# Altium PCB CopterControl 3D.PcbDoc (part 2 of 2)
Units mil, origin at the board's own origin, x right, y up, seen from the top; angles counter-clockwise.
Board outline 1417.32 x 1417.32 mil, 2 copper layers (Top Layer, Bottom Layer), stack 61.2 mil thick; 64 components, 58 nets, 262 pads, 81 vias.
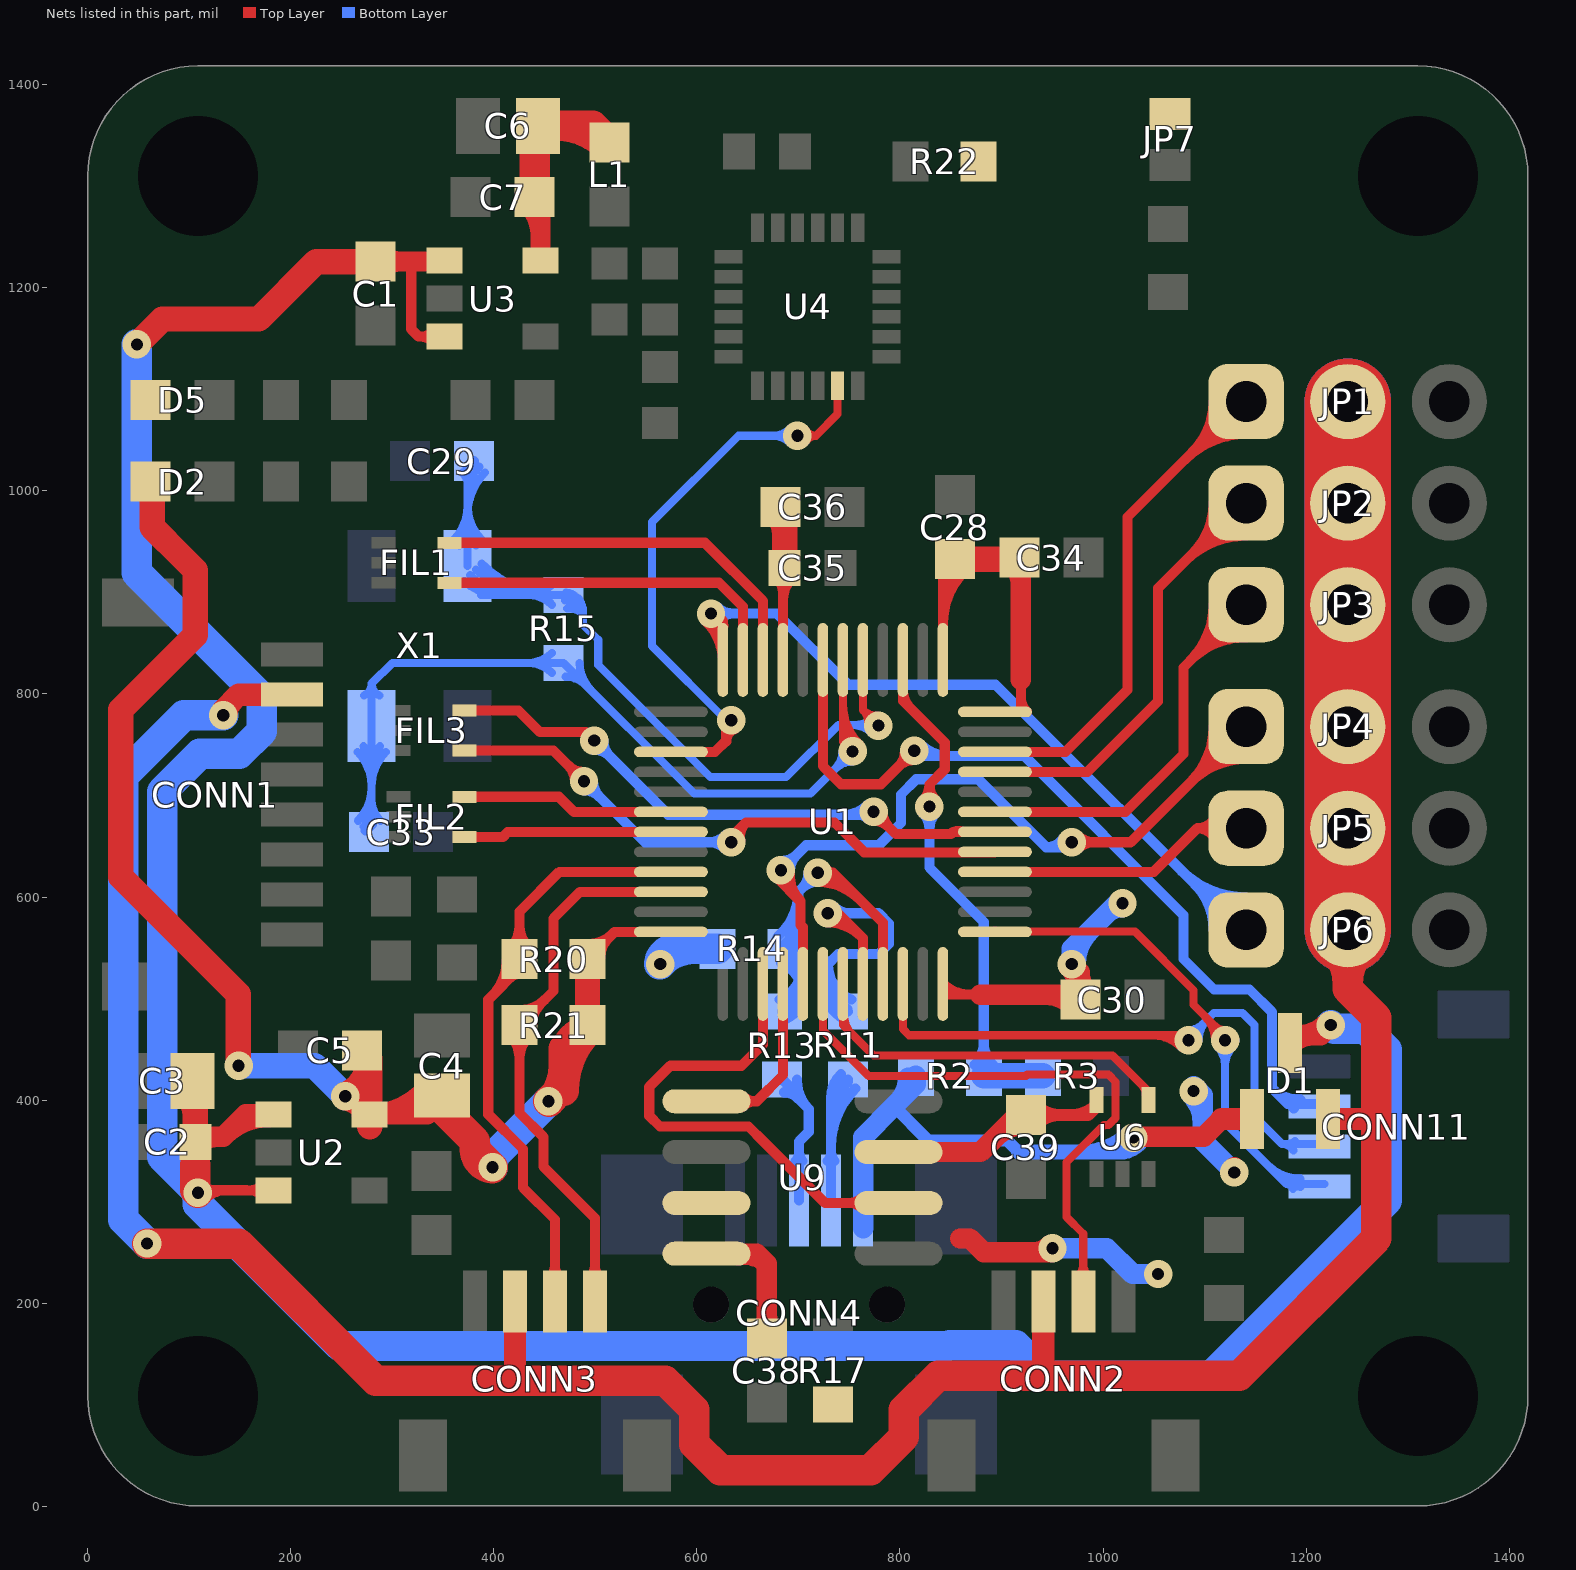
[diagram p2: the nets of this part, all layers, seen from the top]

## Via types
v1: diameter 28, hole 12, Top Layer to Bottom Layer, tented both sides, 81 vias

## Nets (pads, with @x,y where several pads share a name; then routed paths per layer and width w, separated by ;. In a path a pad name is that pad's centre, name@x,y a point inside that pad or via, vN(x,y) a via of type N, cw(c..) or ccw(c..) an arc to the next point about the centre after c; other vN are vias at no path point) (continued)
NetU1_27: U1.27 U9.2 | length 523.8
  Top Layer w10: U1.27@665.1,514.55 665.1,455.1 644,434 574,434 553.2,413.2 553.2,384.8 563.81,374.19 650.91,374.19 665.82,359.28 726.09,299 U9.2@798.49,299 ; U9.2@762.18,294.18 ccw(c750.55,282.56) 750.55,299 ccw(c750.55,315.44) U9.2@762.18,303.82
NetU1_28: U1.28 U9.5 | length 201.6
  Top Layer w10: U9.5@609.51,399 659,399 684.79,424.79 U1.28@684.79,514.55 ; U9.5@645.82,394.18 cw(c657.45,382.56) 657.45,399 cw(c657.45,415.44) U9.5@645.82,403.82
NRST: CONN11.2 U1.7 | length 942.4
  Top Layer w10: U1.7@724.16,833.45 724.16,728.84 742,711 781,711 809,739 814,739 v1(814,744) ; v1@805,744 cw(c783.27,744) 798.64,728.64 cw(c814,713.27) v1@814,735
  Bottom Layer w10: v1(814,744) 814,739 922.18,739 1079,582.18 1079,539 1109,509 1144,509 1166,487 1166,412 ; v1@820.36,750.36 ccw(c847.8,777.8) 847.8,739 ; CONN11.2@1187.64,391.83 ccw(c1181.58,390.12) 1181.58,396.42 ; CONN11.2@1194.13,400.5 cw(c1193.77,439.77) 1166,412 ; CONN11.2@1217.9,396.42 1181.58,396.42 ; 1166,412 1181.58,396.42
OSC_IN: C29.2 R15.2 U1.5 X1.3 | length 1407.7
  Top Layer w8: U1.5@763.53,833.45 763.53,784.07 ; v1@768.83,769.62 ccw(c750.57,771.12) 763.53,784.07 ; v1@777.98,778.77 cw(c776.48,797.02) 763.53,784.07 ; v1(778.8,768.8) 763.53,784.07
  Bottom Layer w8: X1.3@360.64,951.69 ccw(c327.14,985.19) 374.51,985.19 ccw(c421.88,985.19) X1.3@388.38,951.69 ; X1.3@366.29,946.04 ccw(c346.45,965.88) 374.51,965.88 ccw(c402.57,965.88) X1.3@382.73,946.04 ; C29.2@369.4,1017.91 cw(c357.08,1005.58) 374.51,1005.58 ; X1.3@371.41,911.1 ccw(c404.34,944.02) 404.34,897.46 ; X1.3@374.51,926.01 C29.2@374.51,1023.01 ; 374.51,976.68 cw(c432.81,976.68) C29.2@391.59,1017.91 ; 374.51,996 cw(c413.5,996) C29.2@385.93,1023.56 ; X1.3@377.07,916.76 ccw(c423.65,963.34) 423.65,897.47 ; X1.3@382.73,922.41 ccw(c442.96,982.65) 442.96,897.46 ; X1.3@387.47,897.47 R15.2@469,897.47 488,878.46 ; X1.3@388.38,928.07 ccw(c462.28,1001.96) R15.2@462.28,897.46 ; 432.29,902.86 ccw(c438.66,938.28) R15.2@459.2,908.73 ; 436.29,902.14 cw(c430.94,872.37) R15.2@455.77,889.64 ; R15.2@457.33,887.77 ccw(c433.92,864.35) 433.92,897.46 ccw(c433.92,930.58) R15.2@457.33,907.16 ; R15.2@470.42,891.77 cw(c468.57,872.43) 488,872.43 ; R15.2@471.19,899.74 cw(c469.41,881.24) R15.2@488,881.24 ; R15.2@472.55,883.84 cw(c474.72,865.18) 488,878.47 ; R15.2@484.13,893.61 ccw(c498.83,889.3) 488,878.46 ; 753.34,769.34 cw(c753.34,743.34) v1@771.73,761.73 ; 755.97,769.34 ccw(c755.97,791.63) v1@771.73,775.87 ; v1@769.32,765.6 ccw(c764.11,763.84) 764.11,769.34 ; v1@769.7,772.94 cw(c764.11,775.48) 764.11,769.34 ; v1(778.8,768.8) 778.14,768.14 765.31,768.14 764.11,769.34 ; 488,878.46 488,868.23 503,853.23 503,828.23 613.23,718 688,718 739.34,769.34 764.11,769.34
  Bottom Layer w10: C29.2@374.51,1023.01 C29.2@380.5,1029
OSC_OUT: C33.2 R15.1 U1.6 X1.1 | length 1238.7
  Top Layer w8: 743.84,771.11 ccw(c781.11,771.11) v1@754.76,744.76 ; 743.84,790.42 ccw(c800.42,790.42) v1@760.41,750.41 ; U1.6@743.84,833.45 743.84,752.84 v1(753.34,743.34)
  Bottom Layer w8: X1.1@266.15,742.84 cw(c232.65,709.34) 280.02,709.34 cw(c327.39,709.34) X1.1@293.9,742.84 ; C33.2@266.41,675.09 ccw(c233.55,707.95) 280.02,707.95 ; X1.1@271.8,748.5 cw(c251.96,728.66) 280.02,728.66 cw(c308.08,728.66) X1.1@288.24,748.5 ; C33.2@272.07,669.43 ccw(c252.87,688.63) 280.02,688.63 ; X1.1@272.33,798.39 ccw(c267.38,810.02) 280.02,810.02 ; C33.2@280.02,671.52 X1.1@280.02,768.53 280.02,810.02 ; 280.02,695.78 ccw(c309.29,695.78) C33.2@288.59,675.09 ; X1.1@287.71,798.39 cw(c292.66,810.02) 280.02,810.02 ; R15.1@457.33,820.84 ccw(c433.92,797.42) 433.92,830.53 ccw(c433.92,863.65) R15.1@457.33,840.23 ; R15.1@470.97,816.82 cw(c470.97,788.46) 491.02,808.51 ; R15.1@484.68,830.53 ccw(c522.55,830.53) 495.78,803.76 ; v1@743.34,743.34 cw(c719.2,743.34) 736.27,726.27 cw(c753.34,709.2) v1@753.34,733.34 ; v1@754,744 v1(753.34,743.34) 712,702 597.53,702 R15.1@469,830.53 300.53,830.53 280.02,810.02
  Bottom Layer w10: C33.2@274,665.5 C33.2@280.02,671.52
S1_IN: FIL3.5 U1.42 | length 691.1
  Top Layer w10: FIL3.5@371.48,783.69 424.31,783.69 445.68,762.32 490.68,762.32 v1(499,754) ; v1@774,675 cw(c774,653.27) 789.36,668.64 cw(c804.73,684) v1@783,684 ; v1(774,684) 796,662 850.18,662 ; U1.42@862.15,663.96 ccw(c857.54,654.65) 850.18,662 ; U1.42@893.45,664.16 852.34,664.16 850.18,662
  Bottom Layer w10: v1@499,745 cw(c499,723.27) 514.36,738.64 cw(c529.73,754) v1@508,754 ; v1(499,754) 572,681 771,681 v1(774,684) ; 745.03,681 ccw(c745.03,712.97) v1@767.64,690.36 ; 759.51,681 cw(c759.51,669.51) v1@767.64,677.64
S1_OUT: JP1.1 U1.46 | length 694.5
  Top Layer w10: U1.46@893.45,742.9 962.9,742.9 1024,804 1024,974 1137.73,1087.73 JP1.1@1140.73,1087.73 ; 1080.99,1030.99 cw(c1140.73,971.24) JP1.1@1140.73,1055.73 ; 1088.23,1038.23 ccw(c1038.72,1087.73) JP1.1@1108.73,1087.73 ; 1098.06,1048.06 cw(c1140.73,1005.38) JP1.1@1140.73,1065.73 ; 1105.3,1055.3 ccw(c1072.86,1087.73) JP1.1@1118.73,1087.73
S2_IN: FIL3.4 U1.41 | length 704.3
  Top Layer w10: FIL3.4@371.48,744.32 458.68,744.32 v1(489,714) ; v1@480,714 ccw(c458.27,714) 473.64,729.36 ccw(c489,744.73) v1@489,723 ; v1(634,654) 634,659 648.32,673.32 ; v1@642.85,655.65 cw(c662.33,659.3) 648.32,673.32 ; U1.41@893.45,644.47 892.98,644 764.91,644 735.6,673.32 648.32,673.32
  Bottom Layer w10: v1@489,705 cw(c489,683.27) 504.36,698.64 cw(c519.73,714) v1@498,714 ; v1(489,714) 549,654 v1(634,654) ; v1@627.64,647.64 ccw(c612.27,632.27) 612.27,654 ccw(c612.27,675.73) v1@627.64,660.36
S2_OUT: JP2.1 U1.45 | length 626.9
  Top Layer w10: U1.45@893.45,723.21 984.57,723.21 1054,792.64 1054,904 1137.73,987.73 JP2.1@1140.73,987.73 ; 1080.99,930.99 cw(c1140.73,871.24) JP2.1@1140.73,955.73 ; 1088.23,938.23 ccw(c1038.72,987.73) JP2.1@1108.73,987.73 ; 1098.06,948.06 cw(c1140.73,905.38) JP2.1@1140.73,965.73 ; 1105.3,955.3 ccw(c1072.86,987.73) JP2.1@1118.73,987.73
S3_IN: FIL2.5 U1.18 | length 209.2
  Top Layer w10: FIL2.5@371.48,698.69 464.16,698.69 479,683.84 U1.18@574.55,683.84
S3_OUT: JP3.1 U1.43 | length 586.4
  Top Layer w10: U1.43@893.45,683.84 1022.03,683.84 1079,740.82 1079,826 JP3.1@1140.73,887.73 ; JP3.1@1108.73,887.73 cw(c1031.48,887.73) 1086.11,833.11 cw(c1140.73,778.48) JP3.1@1140.73,855.73 ; JP3.1@1118.73,887.73 cw(c1065.62,887.73) 1103.18,850.18 cw(c1140.73,812.62) JP3.1@1140.73,865.73
S4_IN: FIL2.4 U1.19 | length 202.7
  Top Layer w10: FIL2.4@374,659 409,659 414,664 574.39,664 U1.19@574.55,664.16
S4_OUT: JP4.1 U1.29 | length 1069.3
  Top Layer w10: v1@681.78,626.52 ccw(c700.99,624.35) 687.32,610.68 ; v1(682.77,626.41) 681.59,626.41 679.68,628.32 679,629 679,619 702,596 ; v1@691.72,625.4 ccw(c727.37,621.37) 702,596 ; U1.29@704.47,514.55 704.47,570.34 702,572.82 702,596 ; v1(969,654) 1027,654 JP4.1@1140.73,767.73 ; v1@975.36,647.64 cw(c990.73,632.27) 990.73,654 cw(c990.73,675.73) v1@975.36,660.36 ; JP4.1@1108.73,767.73 cw(c1031.48,767.73) 1086.11,713.11 cw(c1140.73,658.48) JP4.1@1140.73,735.73 ; JP4.1@1118.73,767.73 cw(c1065.62,767.73) 1103.18,730.18 cw(c1140.73,692.62) JP4.1@1140.73,745.73
  Bottom Layer w10: v1(682.77,626.41) 681.59,626.41 679.68,628.32 679,629 685.82,629 707.82,651 779.18,651 801,672.82 801,701 816,716 877,716 944,649 ; v1@682.77,635.41 ccw(c682.77,658.22) 698.9,642.09 ; v1@691.77,626.41 cw(c712.42,626.41) 697.82,641 ; v1@961.33,658.7 cw(c944,669.32) 944,649 ; v1(969,654) 964,649 944,649
S5_IN: FIL1.5 U1.10 | length 390.4
  Top Layer w10: FIL1.5@356.48,948.69 607.95,948.69 665.1,891.54 U1.10@665.1,833.45
S5_OUT: JP5.1 U1.40 | length 312.1
  Top Layer w10: U1.40@893.45,624.79 1049.79,624.79 1092.73,667.73 ; JP5.1@1111.2,655.43 ccw(c1092.74,647.74) 1092.74,667.73 ; JP5.1@1111.2,680.04 cw(c1092.74,687.73) 1092.74,667.73 ; JP5.1@1140.73,667.73 1092.73,667.73
S6_IN: FIL1.4 U1.11 | length 351
  Top Layer w10: FIL1.4@356.48,909.32 621.87,909.32 645.42,885.77 U1.11@645.42,833.45
S6_OUT: JP6.1 U1.12 | length 1079.2
  Top Layer w10: v1@607.93,872.36 cw(c571.01,831.97) U1.12@625.73,831.97 ; v1(614,879) 618.54,879 625.73,871.81 U1.12@625.73,833.45 ; v1@614.67,879.74 cw(c591.75,854.65) U1.12@625.73,854.65 ; v1@616.9,870.48 cw(c619.43,863.05) U1.12@626.23,866.97 ; v1@620.3,877.25 cw(c607.7,864.65) U1.12@625.52,864.65
  Bottom Layer w10: v1(614,879) 679,879 749,809 894,809 1135.27,567.73 JP6.1@1140.73,567.73 ; v1@620.36,872.64 cw(c635.73,857.27) 635.73,879 cw(c635.73,900.73) v1@620.36,885.36 ; 1076.77,626.23 ccw(c1140.73,690.19) JP6.1@1140.73,599.73 ; 1089.97,613.03 cw(c1044.68,567.73) JP6.1@1108.73,567.73 ; 1093.84,609.16 ccw(c1140.73,656.05) JP6.1@1140.73,589.73 ; JP6.1@1107.04,595.96 cw(c1078.82,567.73) JP6.1@1118.73,567.73 ; JP6.1@1110.91,592.09 ccw(c1140.73,621.91) JP6.1@1140.73,579.73
SCK: U1.15 U4.23 | length 643
  Top Layer w8: v1(699,1054) 717.23,1054 ; v1@707.43,1048.63 cw(c717.23,1042.38) 717.23,1054 ; v1@707.43,1059.37 ccw(c717.23,1065.62) 717.23,1054 ; U4.23@738.53,1103.41 738.53,1075.3 717.23,1054
  Top Layer w10: U1.15@574.55,742.9 617.9,742.9 629,754 629,769 v1(634,774) ; 629,753.39 cw(c642.18,753.39) v1@637.32,765.63
  Bottom Layer w8: v1(634,774) 629,774 556,847 556,969 641,1054 v1(699,1054) ; v1@691.93,1046.93 ccw(c674.86,1029.86) 674.86,1054 ccw(c674.86,1078.14) v1@691.93,1061.07
SWDCLK: CONN11.4 U1.37 | length 643.2
  Top Layer w8: U1.37@893.72,566 1031.25,566 1089,508.25 1089,494 v1@1120,463 ; 1100.1,482.9 cw(c1076.2,459) v1@1110,459 ; 1109.76,473.24 ccw(c1120,483.49) v1@1120,469
  Top Layer w10: U1.37@893.45,565.73 U1.37@893.72,566 ; v1(1120,459) v1@1120,463
  Bottom Layer w8: v1@1112.93,451.93 cw(c1095.86,434.86) 1120,434.86 cw(c1144.14,434.86) v1@1127.07,451.93 ; v1(1120,459) 1120,378 1180.32,317.68 ; 1161.84,336.16 ccw(c1194.2,368.51) CONN11.4@1194.2,322.76 ; 1175.5,322.5 ccw(c1194.2,341.2) CONN11.4@1194.2,314.76 ; 1181.94,317.68 ccw(c1181.94,327.2) CONN11.4@1188.67,320.47 ; CONN11.4@1186.67,312.85 ccw(c1180.32,311.09) 1180.32,317.68 ; CONN11.4@1217.9,317.68 1180.32,317.68
  Bottom Layer w10: v1(1120,459) v1@1129,459
SWDIO: CONN11.3 U1.34 | length 694.4
  Top Layer w8: U1.34@802.9,514.55 802.9,470.1 809,464 1084,464 v1(1084,459) ; 1047.79,464 cw(c1047.79,422.79) v1@1076.93,451.93 ; 1067.1,464 cw(c1067.1,442.1) v1@1082.59,457.59
  Bottom Layer w8: v1@1084,461.18 1108.82,486 1137,486 1149,474 1149,384 1175.95,357.05 ; v1@1084,469 ccw(c1084,487.87) 1097.34,474.53 ; v1@1094,459 cw(c1123.41,459) 1102.62,479.8 ; 1181.94,357.05 ccw(c1181.94,366.58) CONN11.3@1188.67,359.84 ; CONN11.3@1187.43,350.42 ccw(c1175.95,343.8) 1175.95,357.05 ; CONN11.3@1217.9,357.05 1175.95,357.05
  Bottom Layer w10: v1(1084,459) v1@1084,461.18
TO_REGS: C1.1 C2.1 C3.1 D1.3 U2.1 U2.3 U3.1 U3.3 | length 3563.7
  Top Layer w10: v1@106.56,311.44 156.56,311.44 156.67,311.33 U2.3@183.49,311.33 ; v1@115.36,302.64 cw(c136.62,281.38) 136.62,311.44 ; v1@115.36,315.36 ccw(c124.84,324.84) 124.84,311.44 ; U2.3@173.05,305.82 ccw(c159.75,292.51) 159.75,311.33 ccw(c159.75,330.15) U2.3@173.05,316.84 ; 319,1225.5 319,1159 326.4,1151.6 U3.3@351.76,1151.6 ; U3.3@341.32,1146.09 ccw(c328.02,1132.78) 328.02,1151.6 ccw(c328.02,1170.42) U3.3@341.32,1157.11
  Top Layer w20: C2.1@104,364 106.56,364 134,364 156.13,386.13 U2.1@183.49,386.13 ; 106.56,336.44 C2.1@106.56,359 ; C2.1@110.62,356.9 cw(c127.76,339.77) 127.76,364 ; 135.5,365.5 cw(c178.57,322.43) U2.1@178.57,383.34 ; C1.1@284,1225.5 319,1225.5 350.85,1225.5 U3.1@351.76,1226.4 ; C1.1@290.85,1218.65 cw(c307.38,1202.12) 307.38,1225.5 cw(c307.38,1248.88) C1.1@290.85,1232.35 ; D1.3@1184,456.4 D1.3@1191.6,464 ; D1.3@1185.28,455.12 cw(c1206.72,433.68) 1206.72,464 ; v1@1221.09,476.74 cw(c1191.6,504.49) D1.3@1191.6,464 ; v1(1224,474) 1214,464 D1.3@1191.6,464
  Top Layer w25: v1(49,1144) 74,1169 169,1169 225.5,1225.5 C1.1@284,1225.5 ; C3.1@97.05,406.62 cw(c74.11,383.68) 106.56,383.68 ; C3.1@103.53,419 106.56,415.97 106.56,364 C2.1@106.56,359
  Top Layer w30: 106.56,336.44 106.56,311.44 v1(109,309)
  Bottom Layer w30: v1(49,1144) 49,919 172,796 172,763.26 149.74,741 111,741 73.73,703.73 73.73,344.27 v1(109,309) 109,297.71 248.58,158.13 848.13,158.13 849,159 914,159 944,129 1106.65,129 1279,301.35 1279,449.54 1257.94,470.6 1227.4,470.6 v1(1224,474) ; v1@108,309 ccw(c132.85,309) 115.28,291.43
UART1_RX: U1.31 U6.4 | length 405.8
  Top Layer w8: U1.31@743.84,514.55 743.84,474.16 774,444 1009.11,444 1044.59,408.52 U6.4@1044.59,400.42 ; U1.31@745.06,483.35 ccw(c770.19,483.35) 752.42,465.58 ; 1038.11,415 cw(c1029.42,406.32) U6.4@1041.7,406.32
UART1_TX: CONN2.3 U1.30 | length 631.3
  Top Layer w8: U1.30@724.16,514.55 724.16,468.84 769,424 924,424 925.21,425.21 1005.27,425.21 1012.3,418.18 1012.3,382.65 1005.27,375.62 1000.62,375.62 964,339 964,285 980.42,268.58 CONN2.3@980.42,201.84 ; CONN2.3@974.89,226.06 ccw(c961.56,239.39) 980.42,239.39 ccw(c999.28,239.39) CONN2.3@985.94,226.06
UART3_RX: CONN3.4 R21.1 U1.22 | length 670.4
  Top Layer w10: R21.1@416.54,463.04 cw(c394.84,441.33) 425.54,441.33 cw(c456.24,441.33) R21.1@434.53,463.04 ; R21.1@425.54,488.68 ccw(c425.54,524.14) 450.6,499.07 ; R21.1@438.25,475.97 cw(c464.2,475.97) 445.85,494.32 ; CONN3.4@494.97,225.35 ccw(c483.34,236.98) 499.79,236.98 ccw(c516.23,236.98) CONN3.4@504.6,225.35 ; CONN3.4@499.79,201.84 499.79,284 449,334.79 449,364 425.54,387.46 R21.1@425.54,474 459,507.46 459,579 485.1,605.1 U1.22@574.55,605.1
UART3_TX: CONN3.3 R20.1 U1.21 | length 730
  Top Layer w10: 398.7,502.95 ccw(c364.62,537.03) R20.1@412.82,537.03 ; R20.1@415.77,520.02 ccw(c398.77,537.03) R20.1@422.82,537.03 ; R20.1@416.2,520.45 cw(c425.53,511.11) R20.1@425.53,524.31 ; R20.1@416.54,549.96 ccw(c394.83,571.67) 425.53,571.67 ccw(c456.24,571.67) R20.1@434.53,549.96 ; CONN3.3@455.6,225.35 ccw(c443.97,236.98) 460.42,236.98 ccw(c476.86,236.98) CONN3.3@465.23,225.35 ; CONN3.3@460.42,201.84 460.42,282.58 429,314 429,351.99 394.82,386.17 394.82,499.07 425.53,529.78 R20.1@425.53,539 425.53,585.53 464.79,624.79 U1.21@574.55,624.79
USB_D_N: R11.1 U1.32 | length 533.3
  Top Layer w10: v1@729,575 cw(c729,529.13) 761.44,561.56 ; v1(729,584) 739,584 763.53,559.47 U1.32@763.53,514.55 ; v1@729,585 cw(c729,563.27) 744.36,578.64
  Bottom Layer w10: 729,503.73 ccw(c753.97,503.73) R11.1@744.18,480.76 ; 729,518.86 ccw(c760.42,518.86) R11.1@748.1,489.96 ; v1(729,584) 779,584 789,574 789,554 779,544 739,544 729,534 ; R11.1@734.52,489.75 ccw(c714.88,493.35) 729,507.47 ; v1@735.36,577.64 cw(c750.73,562.27) 750.73,584 cw(c750.73,605.73) v1@735.36,590.36 ; R11.1@746.88,500.18 cw(c746.59,525.05) 729,507.46 ; R11.1@749,487.47 729,507.47 ; R11.1@752.02,499.16 cw(c766.87,534) 729,534 ; 729,507.47 729,534
USB_D_P: R13.1 R14.2 U1.33 | length 764
  Top Layer w10: v1@719,615 cw(c719,557.06) 759.97,598.03 ; v1(719,624) 734,624 ; v1@719,625 cw(c719,591.2) 742.9,615.1 ; v1@726.94,619.77 cw(c734,616) 734,624 ; v1@726.94,628.23 ccw(c734,632) 734,624 ; U1.33@783.21,514.55 783.21,574.79 734,624
  Bottom Layer w10: R14.2@679.31,560.72 ccw(c642.29,605) 700,605 ; R13.1@681.35,499.31 ccw(c668.42,532.46) R14.2@704,532.46 ; R14.2@682.83,535.19 cw(c670.66,504.15) 704,504.15 ; R13.1@684,487.47 704,507.46 ; R13.1@684.98,490 ccw(c674.13,517.83) 704,517.83 ; R14.2@685.72,553.05 ccw(c660.18,583.6) 700,583.6 ; R13.1@686.12,500.18 ccw(c686.41,525.05) 704,507.46 ; R14.2@686.47,544.5 cw(c676.41,518.81) 704,518.81 ; R13.1@688.62,480.68 ccw(c679.83,503.19) 704,503.19 ; R14.2@690.12,553.81 cw(c682.15,533.47) R14.2@704,533.47 ; R13.1@698.48,489.75 cw(c718.11,493.35) 704,507.46 ; v1@710,624 cw(c688.27,624) 703.64,608.64 cw(c719,593.27) v1@719,615 ; v1(719,624) 700,605 ; 700,605 700,561.53 R14.2@687.47,549 R14.2@704,532.46 ; 704,507.46 R14.2@704,532.46
USB_PWR: CONN4.1 D1.1 R2.1 | length 680.9
  Top Layer w20: v1(1029.71,363.29) 1030.42,364 1099,364 1116.6,381.6
  Top Layer w22: 1116.6,381.6 D1.1@1146.6,381.6
  Bottom Layer w12: 794,394 827.52,360.48 905.48,360.48 916.96,349
  Bottom Layer w15: 916.96,349 1015.42,349 v1(1029.71,363.29) ; 979.51,349 ccw(c979.51,413.49) v1@1025.11,367.89 ; 1015.73,349 ccw(c1015.73,377.27) v1@1035.72,357.28 ; v1@1023.21,363.29 cw(c1007.52,363.29) 1018.61,352.2 cw(c1029.71,341.1) v1@1029.71,356.79
  Bottom Layer w20: CONN4.1@763.73,273.78 CONN4.1@763.73,301.21 763.73,363.73 794,394 815.53,415.53 R2.1@815.53,424 ; 797.77,397.77 ccw(c773.51,422.03) R2.1@807.82,422.03
USB_R_N: CONN4.2 R11.2 | length 279.2
  Bottom Layer w10: CONN4.2@728.81,340.06 ccw(c720.54,348.33) 732.23,348.33 ccw(c743.92,348.33) CONN4.2@735.65,340.06 ; CONN4.2@732.23,301.21 732.23,403.76 R11.2@749,420.53 ; 732.23,354.1 cw(c813.47,354.1) R11.2@756.02,411.54 ; 732.23,378.24 cw(c789.33,378.24) R11.2@748.95,418.61 ; 732.23,402.38 cw(c765.19,402.38) R11.2@741.88,425.69
USB_R_P: CONN4.3 R13.2 | length 229.6
  Bottom Layer w10: R13.2@684,420.53 700.73,403.8 700.73,400.73 ; CONN4.3@697.31,340.06 ccw(c689.04,348.33) 700.73,348.33 ccw(c712.42,348.33) CONN4.3@704.16,340.06 ; R13.2@697.73,415.7 ccw(c710.47,410.47) 700.73,400.73 ; R13.2@698.68,420.16 ccw(c737.84,419.02) 710.14,391.32 ; CONN4.3@700.73,301.21 700.73,359.55 710.14,368.96 710.14,391.32 ; 700.73,400.73 710.14,391.32 ; R13.2@685.97,407.82 cw(c685.97,389.29) 699.07,402.39 ccw(c685.97,389.29) R13.2@685.97,407.82
VBUS_SEN: R2.2 R3.2 U1.3 | length 646.8
  Top Layer w10: U1.3@802.9,833.45 802.9,793.29 844.03,752.15 844.03,725.85 829,710.82 v1(829,689) ; U1.3@803.11,802.25 ccw(c825.27,802.25) 809.6,786.58 ; v1@822.64,695.36 ccw(c807.27,710.73) 829,710.73 ccw(c850.73,710.73) v1@835.36,695.36
  Bottom Layer w10: v1@822.64,682.64 cw(c807.27,667.27) 829,667.27 cw(c850.73,667.27) v1@835.36,682.64 ; v1(829,689) 829,629 882.47,575.53 R2.2@882.47,424 ; R2.2@873.47,434.96 ccw(c851.76,456.67) 882.47,456.67 ccw(c913.17,456.67) R2.2@891.46,434.96
  Bottom Layer w25: R2.2@882.47,424 R3.2@940.53,424
VCC: C4.1 C5.1 C28.2 C30.2 C34.2 C35.1 C36.2 C38.1 C39.1 D2.2 D5.2 JP7.2 R14.1 R17.1 R20.2 R21.2 R22.2 U1.1 U1.9 U1.24 U1.36 U1.48 U2.5 U6.5 U9.3 U9.7 U9.8 | length 4161.9
  Top Layer w10: R20.2@492.47,539 519.2,565.73 U1.24@574.55,565.73 ; R20.2@492.47,553.68 ccw(c492.47,589.14) 517.53,564.07 ; R20.2@505.18,540.97 cw(c531.13,540.97) 512.78,559.32 ; C35.1@678.84,914.43 cw(c664.48,900.08) 684.79,900.08 ; U1.9@684.79,833.45 684.79,922.35 C35.1@686.44,924 ; 684.79,892.09 cw(c716.38,892.09) C35.1@694.04,914.43 ; U1.36@842.27,514.55 842.27,505.73 844,504 879,504 ; U1.1@842.27,833.45 842.27,920.77 C28.2@854,932.5 ; U1.1@842.27,868.73 cw(c917.77,868.73) C28.2@864.38,922.12 ; 842.27,892.87 cw(c893.63,892.87) C28.2@857.31,929.19 ; U1.36@842.42,514.7 ccw(c868.26,540.55) 868.26,504 ; U1.48@919,784 919,814 ; 919,796.43 ccw(c938.81,796.43) U1.48@924.8,782.42
  Top Layer w12: C39.1@924,385.5 985.04,385.5 993.41,393.86 U6.5@993.41,400.42 ; C39.1@933.68,375.82 cw(c957.04,352.46) 957.04,385.5 cw(c957.04,418.53) C39.1@933.68,395.17 ; 969.49,385.5 ccw(c969.49,418.43) U6.5@992.78,395.14
  Top Layer w20: U2.5@277.98,386.13 334.6,386.13 C4.1@349,400.53 ; U2.5@277.98,386.13 ccw(c277.98,460.16) C4.1@334.24,412.05 ; 321.4,386.13 ccw(c321.4,423.03) C4.1@349.44,399.05 ; U9.8@609.51,249 659,249 669,239 ; U9.8@641.38,247.23 cw(c647.59,217.59) 669,239 ; C38.1@662.15,172.34 ccw(c645.62,188.88) 669,188.88 ccw(c692.38,188.88) C38.1@675.85,172.34 ; C38.1@670.83,165.49 C38.1@669,165.49 669,239 ; R17.1@734,100.54 R17.1@734,102.33 ; U9.3@798.49,349 879.25,349 915.75,385.5 C39.1@924,385.5 ; 859,264 868.75,264 882.4,250.35 949.31,250.35 950.11,251.16 v1(950.11,254.35) ; 879,504 972.5,504 C30.2@977,499.5 ; 893.38,363.13 cw(c924,332.51) C39.1@924,375.81 ; C34.2@910.66,927.15 cw(c890.51,907.01) 919,907.01 ; C34.2@917.5,934 919,932.51 919,814 ; 919,914.23 cw(c937.28,914.23) C34.2@924.35,927.15 ; 930.8,250.35 ccw(c930.8,273.66) v1@947.28,257.18 ; 942.05,504 cw(c942.05,463.55) C30.2@970.65,492.15 ; v1@966.17,531.17 cw(c940.03,505.03) C30.2@977,505.03 ; v1@967,530.54 cw(c953.58,507.29) C30.2@979.51,514.23 ; C30.2@970.14,505.29 ccw(c954.03,519.03) v1(969,534) 977,526 C30.2@977,499.5 ; C30.2@970.65,505.85 ccw(c955.34,521.17) 977,521.17 ; v1@977,523.6 ccw(c1002.1,523.6) C30.2@984.35,505.85 ; C30.2@977.5,499 C30.2@977,499.5 ; v1(1129,329) v1@1129,334
  Top Layer w25: D2.2@57.42,1003.92 cw(c41.55,988.05) 64,988.05 ; D2.2@64,1009 64,964 94.17,933.83 ; 94.18,933.83 106.19,921.82 106.19,857.6 33.23,784.64 33.23,619.77 148.5,504.5 148.5,434.5 v1(149,434) ; v1@253.45,405.39 ccw(c239.11,441.52) C5.1@277.98,441.52 ; v1@253.76,402.52 cw(c249.19,374.1) U2.5@277.98,374.1 ; C5.1@265.41,443.92 cw(c235.09,413.59) 277.98,413.59 ; C5.1@270.5,449 C5.1@277.98,441.52 ; U2.5@272.76,386.12 ccw(c254,385.22) v1(254,404) 277.98,404 ; U2.5@277.98,386.13 277.98,404 ; R21.2@492.46,474 R20.2@492.47,539 ; C36.2@677.42,978.92 cw(c655.66,957.15) 686.44,957.15 ; C36.2@682.5,984 686.44,980.07 C35.1@686.44,924 ; C28.2@854,932.5 916.01,932.5 C34.2@917.5,934 ; 896.54,932.5 ccw(c896.54,954.96) C34.2@912.42,939.08 ; 277.98,404 C5.1@277.98,441.52
  Top Layer w30: C4.1@349,400.53 349,392.39 381.68,359.71 ; v1@398.57,333.1 cw(c411.09,359.71) 381.68,359.71 ; v1@398.94,333 cw(c400.03,351.32) 381.68,351.32 ; v1(399,334) 381.68,351.32 ; v1(454,399) 469,414 469,450.53 R21.2@492.46,474 ; v1@454.71,398.29 ccw(c420.2,432.8) 469,432.8 ; 469,409.44 cw(c554.19,409.44) R21.2@494.37,470.1 ; 469,440.21 cw(c498.71,440.21) R21.2@492.99,469.36 ; 381.68,351.32 381.68,359.71
  Bottom Layer w20: v1(950.11,254.35) 1003.65,254.35 1029,229 v1(1054,229) ; v1(969,534) 969,549 1014,594 v1(1019,594) ; v1@973,534 cw(c1018.87,534) 986.44,566.44 ; 1003.64,583.64 cw(c1019,568.27) v1@1019,590 ; v1@1086.17,406.17 cw(c1057.62,377.62) 1098,377.62 ; v1(1089,409) 1089,414 1098,405 1098,360 v1(1129,329)
  Bottom Layer w25: v1(149,434) 224,434 v1(254,404)
  Bottom Layer w30: v1@398,334 cw(c419.73,334) 404.36,349.36 ; v1(399,334) 399,344 v1(454,399) ; v1@563,534.07 cw(c579,532.96) 579,549 ; v1@563.29,534.71 cw(c597.8,500.2) 597.8,549 ; v1(564,534) 579,549 ; R14.1@620.53,549 579,549
VCC_ANA: C6.1 C7.1 L1.2 U3.5 | length 318.4
  Top Layer w20: C7.1@433.65,1282.15 cw(c403.24,1251.74) 446.24,1251.74 ; C7.1@440.5,1289 446.24,1283.25 U3.5@446.24,1226.4
  Top Layer w30: C7.1@440.5,1289 440.5,1352.03 447.46,1359 497.66,1359 L1.2@514,1342.66 ; 440.5,1329.71 cw(c466.91,1329.71) C6.1@448.23,1348.39 ; C6.1@463.24,1359 cw(c463.24,1291.9) L1.2@510.69,1339.35
VCC_UNREG: CONN1.2 CONN2.2 CONN3.2 D1.2 JP1.2 JP2.2 JP3.2 JP4.2 JP5.2 JP6.2 | length 3758.4
  Top Layer w22: v1(134,779) 134,784 149.16,799.16 CONN1.2@201.84,799.16 ; v1@137,779 cw(c156.31,779) 142.66,792.66 ; 421.05,124 CONN3.2@421.05,201.84 ; 939,129 941.05,131.05 CONN2.2@941.05,201.84 ; D1.2@1221.4,381.6 1266.4,381.6 1269,379
  Top Layer w30: v1(59,259) 149,259 284,124 421.05,124 569,124 597.59,95.41 597.59,61.67 623.26,36 771,36 803.87,68.87 803.87,95.22 837.65,129 939,129 1134,129 1269,264 1269,379 1269,481.33 1240.73,509.59 JP6.2@1240.73,567.73 ; JP6.2@1225.18,552.18 cw(c1187.62,514.62) 1240.73,514.62 cw(c1293.85,514.62) JP6.2@1256.29,552.18
  Top Layer w85: JP6.2@1240.73,567.73 JP5.2@1240.73,667.73 JP4.2@1240.73,767.73 JP3.2@1240.73,887.73 JP2.2@1240.73,987.73 JP1.2@1240.73,1087.73
  Bottom Layer w30: v1(59,259) 35.73,282.27 35.73,719.47 95.26,779 v1(134,779)
  Bottom Layer w85: JP6.2@1240.73,567.73 JP5.2@1240.73,667.73 JP4.2@1240.73,767.73 JP3.2@1240.73,887.73 JP2.2@1240.73,987.73 JP1.2@1240.73,1087.73
pads on no net: CONN1.0 CONN2.0 CONN3.0 CONN4.4 CONN4.6 U1.2 U1.4 U1.38 U4.2 U4.3 U4.4 U4.5 U4.6 U4.7 U4.14 U4.15 U4.16 U4.17 U4.19 U4.21 U4.22

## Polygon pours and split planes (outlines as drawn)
VCC on Top Layer "Top-VCC" (solid, remove dead copper, pour order 3): 0.73,109 0.73,1309.79 cw(c109,1309.79) 109,1418.06 1309.79,1418.06 cw(c1309.79,1309.79) 1418.06,1309.79 1418.06,109 cw(c1309.79,109) 1309.79,0.73 109,0.73 cw(c109,109)
GND on Bottom Layer "Bottom Layer-GND" (solid, remove dead copper, pour order 4): 0.73,109 0.73,1309.79 cw(c109,1309.79) 109,1418.06 1309.79,1418.06 cw(c1309.79,1309.79) 1418.06,1309.79 1418.06,109 cw(c1309.79,109) 1309.79,0.73 109,0.73 cw(c109,109)

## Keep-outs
Top Layer:
  circle w3.94: c109,109 r59.06
  circle w3.94: c109,109 r106.3
  circle w3.94: c1309.79,109 r59.06
  circle w3.94: c1309.79,109 r106.3
  circle w3.94: c109,1309.79 r59.06
  circle w3.94: c109,1309.79 r106.3
  circle w3.94: c1309.79,1309.79 r106.3
  circle w3.94: c1309.79,1309.79 r59.06
Bottom Layer:
  circle w3.94: c1309.43,1310.73 r106.3
  circle w3.94: c109.43,1310.73 r106.3
  circle w3.94: c109.43,110.73 r106.3
  circle w3.94: c1309.43,110.73 r106.3
Keep-Out Layer:
  the board outline again, w10

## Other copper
Top Layer:
  pour cut-out: 434,1418.06 434,1094 484,1044 774,1044 859,1129 859,1418.06

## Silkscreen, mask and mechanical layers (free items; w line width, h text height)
Top Overlay:
  circle w10: c969,329 r5
  lines w7: 1124,1169 1139,1154 ; 1139,1194 1139,1154 ; 1154,1169 1139,1154
  text "+3.3V" at 1099,1359 h50
  text "" at 919,1319 h137.8
  text "SBL" at 1104,1304 h50
  text "Sig" at 1109,1209 h50
  text "-" at 1330.73,1169.73 h90
  text "+" at 1225.73,1164.73 h80
  text "Status" at 59,1124 h60
  text "1" at 1034,1084 h65
  text "2" at 1034,984 h65
  text "CC3D" at 339,974 h100
  text "Power" at 64,934 h60
  text "3" at 1034,884 h65
  text "4" at 1034,759 h65
  text "5" at 1034,659 h65
  text "6" at 1034,559 h65
  text "Sig" at 1099,474 h50
  text "-" at 1329,454 h90
  text "+" at 1244,449 h80
  text "Flexi" at 209,144 h55
  text "Main" at 1094,144 h50
  text "Port" at 219,104 h55
  text "Port" at 1094,104 h55
Bottom Overlay:
  lines w7: 1129,1164 1144,1149 ; 1144,1209 1144,1149 ; 1159,1164 1144,1149
  text "B" at 587,1320 h160
  text "Rev. C" at 550,1270 h60
  text "Sig" at 1189,1229 h80
  text "-" at 1330.73,1190.73 h90
  text "+" at 1225.73,1185.73 h80
  text "A" at 1059,1124 h300
  text "www.OpenPilot.org" at 35.73,465.73 h60 r270
  text "GND" at 1174,424 h30
  text "NRST" at 1174,389 h30
  text "IO" at 1174,349 h30
  text "CLK" at 1174,294 h30
  text "SWD" at 1324,179 h40
  text "Copter" at 1230.73,120.73 h80
  text "3D" at 415.73,65.73 h120
  text "Control" at 1230.73,50.73 h80
Mechanical 1:
  the board outline again, w10
Mechanical 15:
  lines w7: 604,1076.17 604,1286.17 814,1286.17 814,1076.17 604,1076.17
Mechanical 16:
  lines w10: 239,709 414,709 414,984 239,984 239,709

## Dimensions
0.73,-18.95 to 1418.06,-28.79 on Dimensions
109,-18.95 to 1309.79,-18.95 on Dimensions
-18.95,109 to -18.95,1309.79 on Dimensions
-18.95,0.73 to -18.95,1418.06 on Dimensions
1268.03,1351.55 to -2431,-1944 on Dimensions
